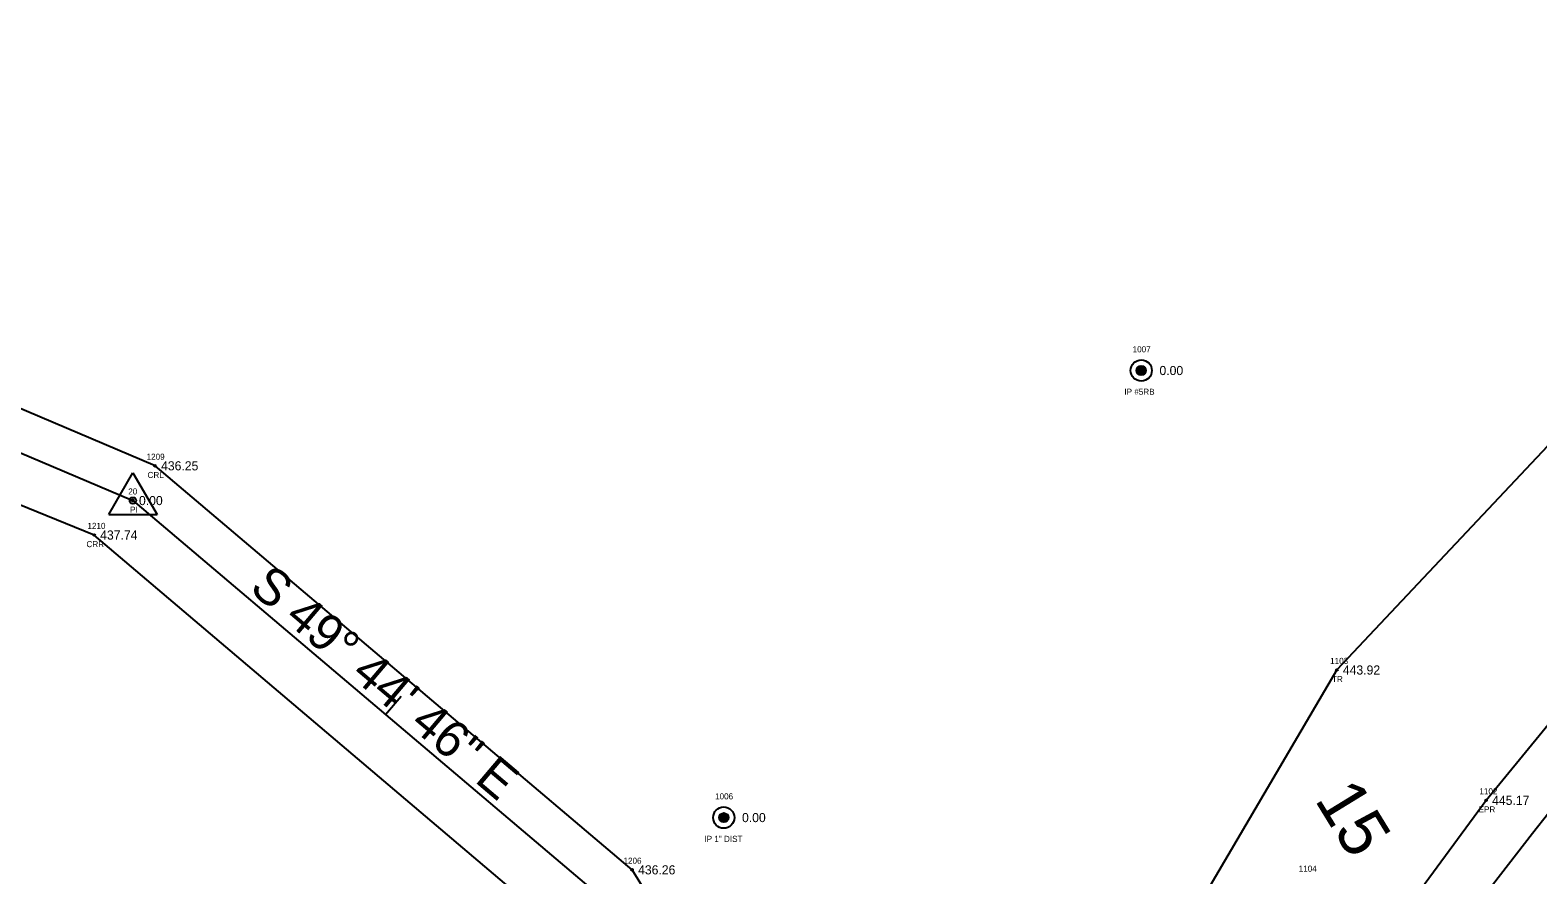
# Model space of a CAD drawing. Extents: x 1762456 to 1764480, y 822234 to 826541.
# Drawn here: x 1763302.6 to 1763550.9, y 824906.9 to 825046 of the extents above; entities that cross this region are included whole.
import ezdxf

# ---------------------------------------------------------------- set-up
doc = ezdxf.new("R2010")
doc.units = 0
for name, color, linetype in [('RD_EX_DR_Pipe_txCode', 7, 'Continuous'), ('RD_EX_DV_Prop_txCode', 7, 'Continuous'), ('RD_EX_DV_PropPin', 7, 'Continuous'), ('RD_EX_H2O', 7, 'Continuous'), ('RD_EX_H2O_txCode', 7, 'Continuous'), ('RD_EX_Road', 7, 'Continuous'), ('RD_EX_Road_txCode', 7, 'Continuous'), ('RD_EX_TX_DV_Prop_ELEV', 7, 'Continuous'), ('RD_EX_TX_H2O_ELEV', 7, 'Continuous'), ('RD_EX_TX_Road_ELEV', 7, 'Continuous'), ('RD_EX_TX_VEG_ELEV', 7, 'Continuous'), ('RD_EX_VEG', 7, 'Continuous'), ('RD_EX_VEG_txCode', 7, 'Continuous'), ('RD_HC_Cl', 7, 'Continuous'), ('RD_HC_Data', 7, 'Continuous'), ('RD_HC_Data_Tic', 7, 'Continuous'), ('RD_HC_Survey_ELEV', 7, 'Continuous'), ('RD_HC_TX_Sta50', 7, 'Continuous'), ('RD_HC_txCode', 7, 'Continuous'), ('RD_SMD_Locator', 7, 'Continuous')]:
    doc.layers.add(name, color=color, linetype=linetype)

msp = doc.modelspace()

# ---------------------------------------------------------------- linework, layer by layer
at = {"layer": 'RD_EX_DV_PropPin'}
for p, q in [((1763484.86, 824989.76), (1763484.86, 824990.15)), ((1763484.89, 824989.66), (1763484.89, 824990.26)), ((1763484.93, 824989.59), (1763484.93, 824990.33)), ((1763484.96, 824989.53), (1763484.96, 824990.38)), ((1763485, 824989.48), (1763485, 824990.43)), ((1763485.03, 824989.44), (1763485.03, 824990.47)), ((1763485.07, 824989.41), (1763485.07, 824990.51)), ((1763485.1, 824989.38), (1763485.1, 824990.54)), ((1763485.14, 824989.35), (1763485.14, 824990.57)), ((1763485.17, 824989.32), (1763485.17, 824990.59)), ((1763485.21, 824989.3), (1763485.21, 824990.61)), ((1763485.24, 824989.28), (1763485.24, 824990.63)), ((1763485.28, 824989.27), (1763485.28, 824990.65)), ((1763485.31, 824989.25), (1763485.31, 824990.67)), ((1763485.35, 824989.24), (1763485.35, 824990.68)), ((1763485.38, 824989.23), (1763485.38, 824990.69)), ((1763485.42, 824989.22), (1763485.42, 824990.7)), ((1763485.45, 824989.21), (1763485.45, 824990.71)), ((1763485.49, 824989.2), (1763485.49, 824990.71)), ((1763485.52, 824989.2), (1763485.52, 824990.72)), ((1763485.56, 824989.2), (1763485.56, 824990.72)), ((1763485.59, 824989.2), (1763485.59, 824990.72)), ((1763485.63, 824989.2), (1763485.63, 824990.72)), ((1763485.66, 824989.2), (1763485.66, 824990.72)), ((1763485.7, 824989.2), (1763485.7, 824990.71)), ((1763485.73, 824989.21), (1763485.73, 824990.71)), ((1763485.77, 824989.22), (1763485.77, 824990.7)), ((1763485.8, 824989.23), (1763485.8, 824990.69)), ((1763485.84, 824989.24), (1763485.84, 824990.68)), ((1763485.87, 824989.25), (1763485.87, 824990.67)), ((1763485.91, 824989.27), (1763485.91, 824990.65)), ((1763485.94, 824989.28), (1763485.94, 824990.63)), ((1763485.98, 824989.3), (1763485.98, 824990.61)), ((1763486.01, 824989.32), (1763486.01, 824990.59)), ((1763486.05, 824989.35), (1763486.05, 824990.57)), ((1763486.08, 824989.38), (1763486.08, 824990.54)), ((1763486.12, 824989.41), (1763486.12, 824990.51)), ((1763486.15, 824989.44), (1763486.15, 824990.47)), ((1763486.19, 824989.48), (1763486.19, 824990.43)), ((1763486.22, 824989.53), (1763486.22, 824990.38)), ((1763486.26, 824989.59), (1763486.26, 824990.33)), ((1763486.29, 824989.66), (1763486.29, 824990.26)), ((1763486.33, 824989.76), (1763486.33, 824990.15)), ((1763416.26, 824915.89), (1763416.26, 824916.84)), ((1763416.29, 824915.85), (1763416.29, 824916.88)), ((1763416.33, 824915.81), (1763416.33, 824916.91)), ((1763416.36, 824915.78), (1763416.36, 824916.94)), ((1763416.4, 824915.75), (1763416.4, 824916.97)), ((1763416.43, 824915.73), (1763416.43, 824917)), ((1763416.47, 824915.7), (1763416.47, 824917.02)), ((1763416.5, 824915.69), (1763416.5, 824917.04)), ((1763416.54, 824915.67), (1763416.54, 824917.05)), ((1763416.57, 824915.65), (1763416.57, 824917.07)), ((1763416.61, 824915.64), (1763416.61, 824917.08)), ((1763416.64, 824915.63), (1763416.64, 824917.09)), ((1763416.68, 824915.62), (1763416.68, 824917.1)), ((1763416.71, 824915.61), (1763416.71, 824917.11)), ((1763416.75, 824915.61), (1763416.75, 824917.11)), ((1763416.78, 824915.6), (1763416.78, 824917.12)), ((1763416.82, 824915.6), (1763416.82, 824917.12)), ((1763416.85, 824915.6), (1763416.85, 824917.12)), ((1763416.89, 824915.6), (1763416.89, 824917.12)), ((1763416.92, 824915.6), (1763416.92, 824917.12)), ((1763416.96, 824915.61), (1763416.96, 824917.11)), ((1763416.99, 824915.61), (1763416.99, 824917.11)), ((1763417.03, 824915.62), (1763417.03, 824917.1)), ((1763417.06, 824915.63), (1763417.06, 824917.09)), ((1763417.1, 824915.64), (1763417.1, 824917.08)), ((1763417.13, 824915.65), (1763417.13, 824917.07)), ((1763417.17, 824915.67), (1763417.17, 824917.05)), ((1763417.2, 824915.69), (1763417.2, 824917.04)), ((1763417.24, 824915.7), (1763417.24, 824917.02)), ((1763417.27, 824915.73), (1763417.27, 824917)), ((1763417.31, 824915.75), (1763417.31, 824916.97)), ((1763417.34, 824915.78), (1763417.34, 824916.94)), ((1763417.38, 824915.81), (1763417.38, 824916.91)), ((1763417.42, 824915.85), (1763417.42, 824916.88)), ((1763417.45, 824915.89), (1763417.45, 824916.84)), ((1763416.12, 824916.17), (1763416.12, 824916.56)), ((1763416.15, 824916.06), (1763416.15, 824916.66)), ((1763416.19, 824915.99), (1763416.19, 824916.73)), ((1763416.22, 824915.93), (1763416.22, 824916.79)), ((1763417.49, 824915.93), (1763417.49, 824916.79)), ((1763417.52, 824915.99), (1763417.52, 824916.73)), ((1763417.56, 824916.06), (1763417.56, 824916.66)), ((1763417.59, 824916.17), (1763417.59, 824916.56))]:
    msp.add_line(p, q, dxfattribs=at)
for centre, radius in [((1763485.59, 824989.96), 1.75), ((1763485.59, 824989.96), 0.761), ((1763416.85, 824916.36), 1.75), ((1763416.85, 824916.36), 0.761)]:
    msp.add_circle(centre, radius, dxfattribs=at)
at = {"layer": 'RD_EX_H2O'}
for points in [[(1763469.64, 824827.68), (1763444.91, 824845.55), (1763435.48, 824853.42), (1763401.74, 824907.76), (1763323.19, 824974.27), (1763226.75, 825015.18), (1763219.02, 825018.48), (1763206.39, 825014.43), (1763109.02, 824967.64), (1763091.9, 824957.32), (1763081.74, 824947.35), (1763046.14, 824865.15)], [(1763459.77, 824813.09), (1763437.3, 824833.98), (1763421.73, 824846.89), (1763391.2, 824896.67), (1763313.16, 824962.88), (1763227.9, 824997.52), (1763208.46, 824998.22), (1763114.18, 824952.92), (1763092.86, 824935.95), (1763064.35, 824852.13)]]:
    msp.add_lwpolyline(points, dxfattribs=at)
at = {"layer": 'RD_EX_Road'}
msp.add_lwpolyline([(1763951.03, 825365.44), (1763882.12, 825291.59), (1763813.3, 825217.44), (1763784.22, 825184.64), (1763754.38, 825152.48), (1763744.67, 825142.84), (1763675.27, 825070.17), (1763607.46, 824995.53), (1763574.27, 824958.09), (1763542.37, 824919.2), (1763512.11, 824877.96), (1763483.2, 824837.35)], dxfattribs=at)
at = {"layer": 'RD_EX_VEG'}
msp.add_lwpolyline([(1763566.8, 824996.31), (1763552.48, 824977.49), (1763517.79, 824940.66), (1763441.02, 824809.92), (1763409.91, 824765.77), (1763387.31, 824719.59), (1763364.33, 824675.15), (1763345.2, 824627.76), (1763325.76, 824580.46), (1763306.34, 824535.9), (1763266.94, 824443.24), (1763235.97, 824345.2), (1763198.02, 824250.85), (1763166.5, 824157.97)], dxfattribs=at)
at = {"layer": 'RD_HC_Cl'}
for p, q in [((1763226.45, 825008.07), (1763319.55, 824968.55)), ((1763319.55, 824968.55), (1763397.8, 824902.3))]:
    msp.add_line(p, q, dxfattribs=at)
msp.add_arc((1764677.02, 824029.63), 1432.39, 137.05318, 159.11763, dxfattribs=at)
at = {"layer": 'RD_HC_Data'}
for p, q in [((1763315.58, 824966.25), (1763319.55, 824973.13)), ((1763319.55, 824973.13), (1763323.52, 824966.25)), ((1763315.58, 824966.25), (1763323.52, 824966.25))]:
    msp.add_line(p, q, dxfattribs=at)
msp.add_circle((1763319.55, 824968.55), 0.529, dxfattribs=at)
at = {"layer": 'RD_HC_Data_Tic'}
msp.add_line((1763361.16, 824933.32), (1763363.74, 824936.37), dxfattribs=at)
at = {"layer": 'RD_SMD_Locator'}
for centre in [(1763485.59, 824989.96), (1763323.19, 824974.27), (1763319.55, 824968.55), (1763313.16, 824962.88), (1763517.79, 824940.66), (1763542.37, 824919.2), (1763416.85, 824916.36), (1763401.74, 824907.76)]:
    msp.add_circle(centre, 0.15, dxfattribs=at)

# ---------------------------------------------------------------- texts
at = {"layer": 'RD_EX_DR_Pipe_txCode'}
msp.add_text('1104', height=1, dxfattribs=at).set_placement((1763511.52, 824907.46))
at = {"layer": 'RD_EX_DV_Prop_txCode'}
for s, p in [('1007', (1763484.17, 824992.96)), ('IP #5RB', (1763482.81, 824985.96)), ('1006', (1763415.41, 824919.36)), ('IP 1" DIST', (1763413.66, 824912.36))]:
    msp.add_text(s, height=1, dxfattribs=at).set_placement(p)
at = {"layer": 'RD_EX_H2O_txCode'}
for s, p in [('1209', (1763321.8, 824975.27)), ('CRL', (1763321.96, 824972.27)), ('1210', (1763312.06, 824963.88)), ('CRR', (1763311.91, 824960.88)), ('1206', (1763400.33, 824908.76))]:
    msp.add_text(s, height=1, dxfattribs=at).set_placement(p)
at = {"layer": 'RD_EX_Road_txCode'}
for s, p in [('1102', (1763541.27, 824920.2)), ('EPR', (1763541.14, 824917.2))]:
    msp.add_text(s, height=1, dxfattribs=at).set_placement(p)
at = {"layer": 'RD_EX_TX_DV_Prop_ELEV'}
for p in [(1763488.59, 824989.21), (1763419.85, 824915.61)]:
    msp.add_text('0.00', height=1.5, dxfattribs=at).set_placement(p)
at = {"layer": 'RD_EX_TX_H2O_ELEV'}
for s, p in [('436.25', (1763324.19, 824973.52)), ('437.74', (1763314.16, 824962.13)), ('436.26', (1763402.74, 824907.01))]:
    msp.add_text(s, height=1.5, dxfattribs=at).set_placement(p)
at = {"layer": 'RD_EX_TX_Road_ELEV'}
msp.add_text('445.17', height=1.5, dxfattribs=at).set_placement((1763543.37, 824918.45))
at = {"layer": 'RD_EX_TX_VEG_ELEV'}
msp.add_text('443.92', height=1.5, dxfattribs=at).set_placement((1763518.79, 824939.91))
at = {"layer": 'RD_EX_VEG_txCode'}
for s, p in [('1103', (1763516.69, 824941.66)), ('TR', (1763517, 824938.66))]:
    msp.add_text(s, height=1, dxfattribs=at).set_placement(p)
at = {"layer": 'RD_HC_Data'}
msp.add_text('S 49%%d 44\' 46" E', height=6, rotation=319.746, dxfattribs=at).set_placement((1763338.53, 824953.79))
at = {"layer": 'RD_HC_Survey_ELEV'}
msp.add_text('0.00', height=1.5, dxfattribs=at).set_placement((1763320.55, 824967.8))
at = {"layer": 'RD_HC_TX_Sta50'}
msp.add_text('15', height=8, rotation=301.509, dxfattribs=at).set_placement((1763514.04, 824919.33))
at = {"layer": 'RD_HC_txCode'}
for s, p in [('20', (1763318.78, 824969.55)), ('PI', (1763319.08, 824966.55))]:
    msp.add_text(s, height=1, dxfattribs=at).set_placement(p)

doc.saveas('drawing.dxf')
